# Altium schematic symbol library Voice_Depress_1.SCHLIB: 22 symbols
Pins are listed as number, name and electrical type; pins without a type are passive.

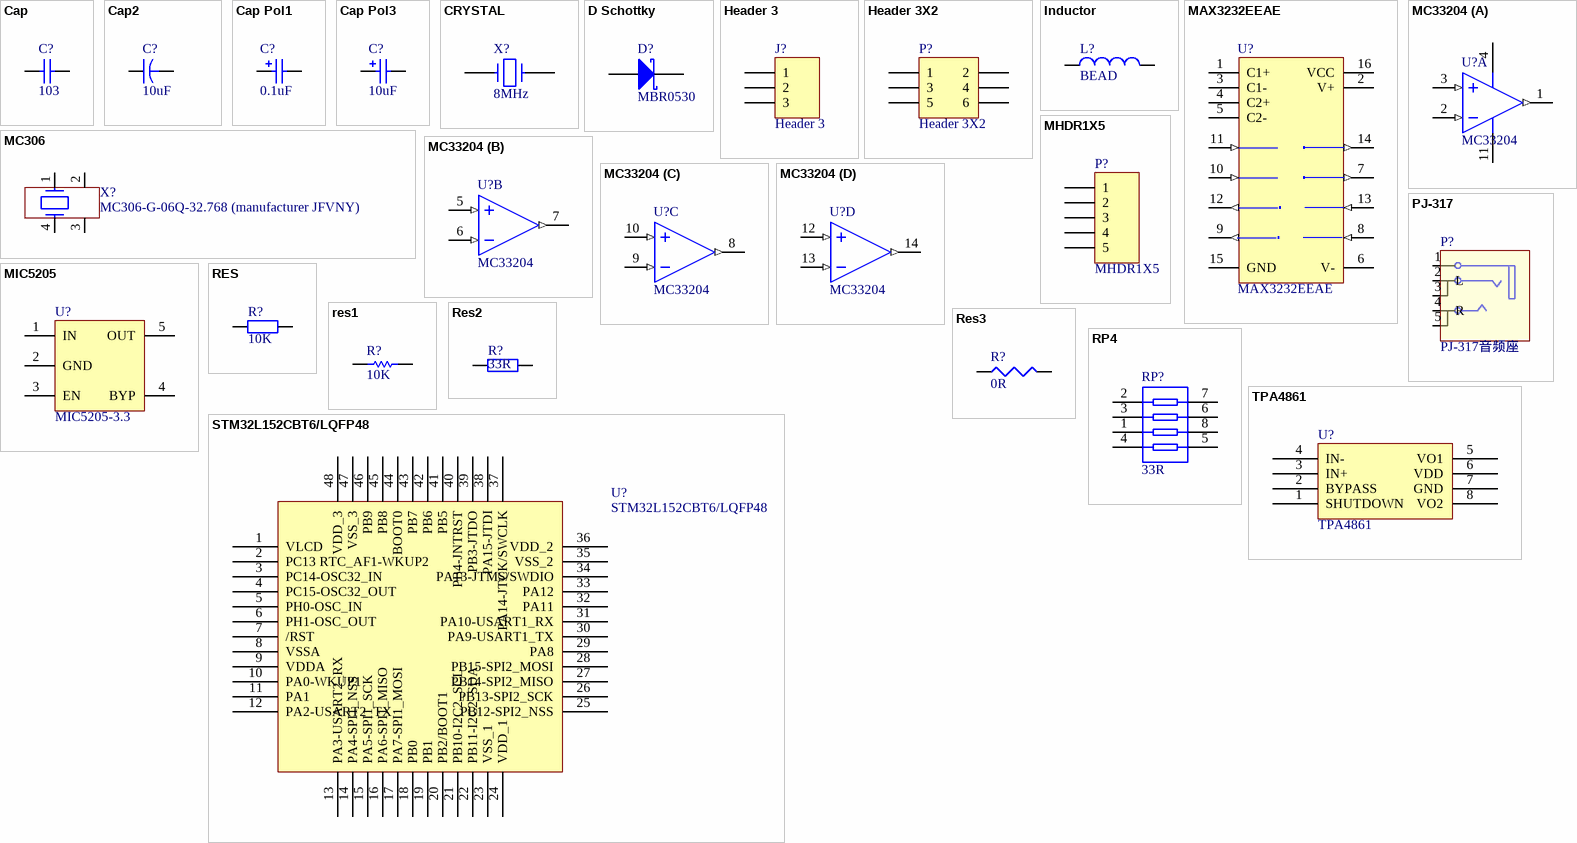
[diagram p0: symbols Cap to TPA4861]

## Cap
designator C?, comment 103
Capacitor
footprint RAD-0.3 (Capacitor; 2 Leads)
footprint CAPR2.54-5.1x3.2 (Capacitor, Ceramic, Thru-Hole, Dipped Radial; Body 5.1 x 3.2 mm (WxT) Pin Spacing 2.54 mm (typ))
footprint CAPR5.08-7.8x3.2 (Capacitor, Ceramic, Thru-Hole, Dipped Radial; Body 7.8 x 3.2 mm (WxT) Pin Spacing 5.08 mm (typ))
simulation model CAP (Capacitor)
signal-integrity model Cap
footprint CR2012-0805
footprint 2012[0805]
footprint CR1608-0603
footprint 1608[0603] (Chip Capacitor; Body 1.6 x 0.8 mm (LxW typ))
footprint R0603
footprint C0603
pins: 1, 2

## Cap2
designator C?, comment 10uF
Capacitor
footprint 1608[0603] (Chip Capacitor; Body 1.6 x 0.8 mm (LxW typ))
simulation model CAP (Capacitor)
signal-integrity model Cap
pins: 1, 2

## Cap Pol1
designator C?, comment 0.1uF
Polarized Capacitor (Radial)
footprint RB7.6-15 (Polarized Capacitor (Radial); 2 Leads)
footprint HA-C1 (Capacitor, Radial, Tantalum; Body 1.7 x 2.8 mm (Dia.xH max); Pin Spacing 1.27 mm (typ))
footprint A (Capacitor, Electrolytic, Radial; Body 4 x 5 mm (Dia.xH typ); Pin Spacing 1.5 mm (typ))
footprint B (Capacitor, Electrolytic, Radial; Body 5 x 6.8 mm (Dia.xH typ); Pin Spacing 2 mm (typ))
footprint CAPPR5-5x5 (Capacitor, Electrolytic, Radial; Body 5 x 5 mm (Dia.xH typ); Pin Spacing 5 mm (typ))
footprint CAPPR7.5-16x35 (Capacitor, Electrolytic, Radial; Body 16 x 35 mm (Dia.xH typ); Pin Spacing 7.5 mm (typ))
simulation model CAP (Capacitor)
signal-integrity model Cap Pol
footprint 0603
footprint B0603
footprint C0603
pins: 1, 2
1 alternate drawing of the same symbol

## Cap Pol3
designator C?, comment 10uF
Polarized Capacitor (Surface Mount); Value: 100pF
simulation model CAP (Capacitor)
footprint 7227
footprint 贴片电容器47u/16V
footprint 3225[1210] (Chip Resistor; Body 3.2 x 2.5 mm (LxW typ))
footprint 6-0805 (Chip Resistor; Body 2.0 x 1.3 mm (LxW typ))
footprint [1608]0603
footprint 6-0805 (Chip Resistor; Body 2.0 x 1.3 mm (LxW typ))
pins: 1, 2
1 alternate drawing of the same symbol

## CRYSTAL
designator X?, comment 8MHz
Crystal
footprint XTAL-CJ
pins: 1, 2
2 alternate drawings of the same symbol

## D Schottky
designator D?, comment MBR0530
Schottky Diode
footprint 3216[1206] (Chip Resistor; Body 3.2 x 1.6 mm (LxW typ))
simulation model SKYDIODE (Diode)
signal-integrity model D Schottky
footprint 1608[0603] (Chip Capacitor; Body 1.6 x 0.8 mm (LxW typ))
pins: 1 A, 2 K

## Header 3
designator J?
Header, 3-Pin
footprint HDR1X3 (Connector; Header; 3 Position)
signal-integrity model Connector
pins: 1, 2, 3

## Header 3X2
designator P?
Header, 3-Pin, Dual row
footprint HDR2X3 (Connector; Header; 3x2 Position)
signal-integrity model Connector
pins: 1, 2, 3, 4, 5, 6

## Inductor
designator L?, comment BEAD
Inductor; Code_IEC: 1005; Value: 10mH
footprint 0402-A (Chip Inductor; Body 1 x 0.5 mm (LxW typ))
footprint L0603 (Chip Inductor; Body 1.6 x 0.8 mm (LxW typ))
footprint 2012_Chip (2012 Chip; Chip Inductor; Body 2.0 x 1.2 mm (LxW typ))
footprint 2029 (Chip Inductor; Body 2 x 1.2 mm (LxW typ))
footprint 3261 (3216 Chip; Chip Inductor; Body 3.2 x 1.6 mm (LxW typ))
footprint 4564_Chip (4564 Chip; Chip Inductor; Body 4.5 x 6.4 mm (LxW typ))
simulation model INDUCTOR (Inductor)
signal-integrity model Inductor
pins: 1, 2

## MAX3232EEAE
designator U?
?5kV ESD-Protected, 3.0V to 5.5V, Low-Power, up to 250kbps, True RS-232 Transceiver
footprint SSOP16 (SSOP; 16 Leads; Body Width 5.3 mm; Pitch 0.65 mm)
3D model SSOP16 (SSOP; 16 Leads; Body Width 5.3 mm; Pitch 0.65 mm)
footprint SSOP16
pins: 1 C1+, 2 V+ (power), 3 C1-, 4 C2+, 5 C2-, 6 V- (power), 7 T2OUT (out), 8 R2IN (in), 9 R2OUT (out), 10 T2IN (in), 11 T1IN (in), 12 R1OUT (out), 13 R1IN (in), 14 T1OUT (out), 15 GND (power), 16 VCC (power)

## MC306
designator X?, comment MC306-G-06Q-32.768 (manufacturer JFVNY)
footprint SM8 (Footprint not found)
footprint 32.768K-MC146 (XTAL-32.768K)
pins: 1, 2, 3, 4

## MC33204
designator U?
part A pins: 1 OUT1 (out), 2 IN1- (in), 3 IN1+ (in), 4 V+ (power), 11 V- (power)
part B pins: 5 IN1+ (in), 6 IN1- (in), 7 OUT1 (out)
part C pins: 8 OUT1 (out), 9 IN1- (in), 10 IN1+ (in)
part D pins: 12 IN1+ (in), 13 IN1- (in), 14 OUT1 (out)

## MHDR1X5
designator P?
Header, 5-Pin
footprint MHDR1X5 (Connector; Header; 5 Position)
signal-integrity model Connector
pins: 1, 2, 3, 4, 5

## MIC5205
designator U?, comment MIC5205-3.3
800mA Low Dropout Positive Regulator Fixed 2.85V,3V,3.3V and 5V; PackageDocument: revC
footprint SOT23-5 (SOT-23/SC-74A; 5 Leads; Body 3 x 3 mm, inc. leads (LxW max))
footprint DSO-G3 (SOT-223/SC-73; 4 Leads; Body 6.7 x 7.3 mm, inc. leads (LxW max))
footprint SOT23-5 (SOT-23/SC-74A; 5 Leads; Body 3 x 3 mm, inc. leads (LxW max))
footprint SOT23-5 (SOT-23/SC-74A; 5 Leads; Body 3 x 3 mm, inc. leads (LxW max))
pins: 1 IN (power), 2 GND (power), 3 EN (power), 4 BYP (power), 5 OUT (power)

## PJ-317
designator P?, comment PJ-317音频座
footprint PJ-317 (音频座)
pins: 1 S (power) "Sleeve (Ground)", 2 L, 3 L, 4 R, 5 R

## RES
designator R?, comment 10K
footprint R-0603
footprint R-0805
footprint 1608[0603] (Footprint not found)
footprint 2012[0805]
footprint C0603
footprint R0603
pins: 1, 2

## res1
designator R?, comment 10K
Resistor; Value: 1K
footprint AXIAL-0.3 (Resistor; 2 Leads)
simulation model RESISTOR (Resistor)
signal-integrity model Res
footprint 0603
footprint 1608[0603]
footprint C0603
footprint R0603
pins: 1, 2
1 alternate drawing of the same symbol

## Res2
designator R?, comment 33R
Resistor
footprint AXIAL-0.4 (Resistor; 2 Leads)
simulation model RESISTOR (Resistor)
signal-integrity model Res
footprint 0603
footprint R0603
pins: 1, 2

## Res3
designator R?, comment 0R
Resistor; Value: 1K
footprint J1-0603 (Chip Resistor; Body 1.6 x 0.8 mm (LxW typ))
footprint 3225[1210] (Chip Resistor; Body 3.2 x 2.5 mm (LxW typ))
footprint 5025[2010] (Chip Resistor; Body 5.0 x 2.5 mm (LxW typ))
footprint 6332[2512] (Chip Resistor; Body 6.3 x 3.2 mm (LxW typ))
simulation model RESISTOR (Resistor)
signal-integrity model Res
footprint 0603
footprint [0603]
pins: 1, 2

## RP4
designator RP?, comment 33R
footprint RP4-0603
pins: 1, 2, 3, 4, 5, 6, 7, 8

## STM32L152CBT6/LQFP48
designator U?
footprint LQFP48_M (Thin QFP, 48-Leads, Body 7x7mm, Pitch 0.5mm, IPC Low Density)
pins: 1 VLCD, 2 PC13 RTC_AF1-WKUP2, 3 PC14-OSC32_IN, 4 PC15-OSC32_OUT, 5 PH0-OSC_IN, 6 PH1-OSC_OUT, 7 /RST, 8 VSSA, 9 VDDA, 10 PA0-WKUP1, 11 PA1, 12 PA2-USART2_TX, 13 PA3-USART2_RX, 14 PA4-SPI1_NSS, 15 PA5-SPI1_SCK, 16 PA6-SPI1_MISO, 17 PA7-SPI1_MOSI, 18 PB0, 19 PB1, 20 PB2/BOOT1, 21 PB10-I2C2_SCL, 22 PB11-I2C2_SDA, 23 VSS_1, 24 VDD_1, 25 PB12-SPI2_NSS, 26 PB13-SPI2_SCK, 27 PB14-SPI2_MISO, 28 PB15-SPI2_MOSI, 29 PA8, 30 PA9-USART1_TX, 31 PA10-USART1_RX, 32 PA11, 33 PA12, 34 PA13-JTMS/SWDIO, 35 VSS_2, 36 VDD_2, 37 PA14-JTCK/SWCLK, 38 PA15-JTDI, 39 PB3-JTDO, 40 PB4-JNTRST, 41 PB5, 42 PB6, 43 PB7, 44 BOOT0, 45 PB8, 46 PB9, 47 VSS_3, 48 VDD_3

## TPA4861
designator U?
1W_AUDIO_AMP
footprint D014_M (SOIC, 14-Leads, Body 8.7x3.9mm, Pitch 1.27mm, IPC Low Density)
pins: 1 SHUTDOWN, 2 BYPASS, 3 IN+, 4 IN-, 5 VO1, 6 VDD, 7 GND, 8 VO2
